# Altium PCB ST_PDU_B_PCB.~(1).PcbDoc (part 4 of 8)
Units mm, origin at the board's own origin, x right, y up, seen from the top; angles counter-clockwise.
Board outline 200 x 200 mm, 6 copper layers (Top Layer, Layer 1, Layer 2, Layer 3, Layer 4, Bottom Layer), stack 3.194 mm thick; 894 components, 723 nets, 3233 pads, 4067 vias.
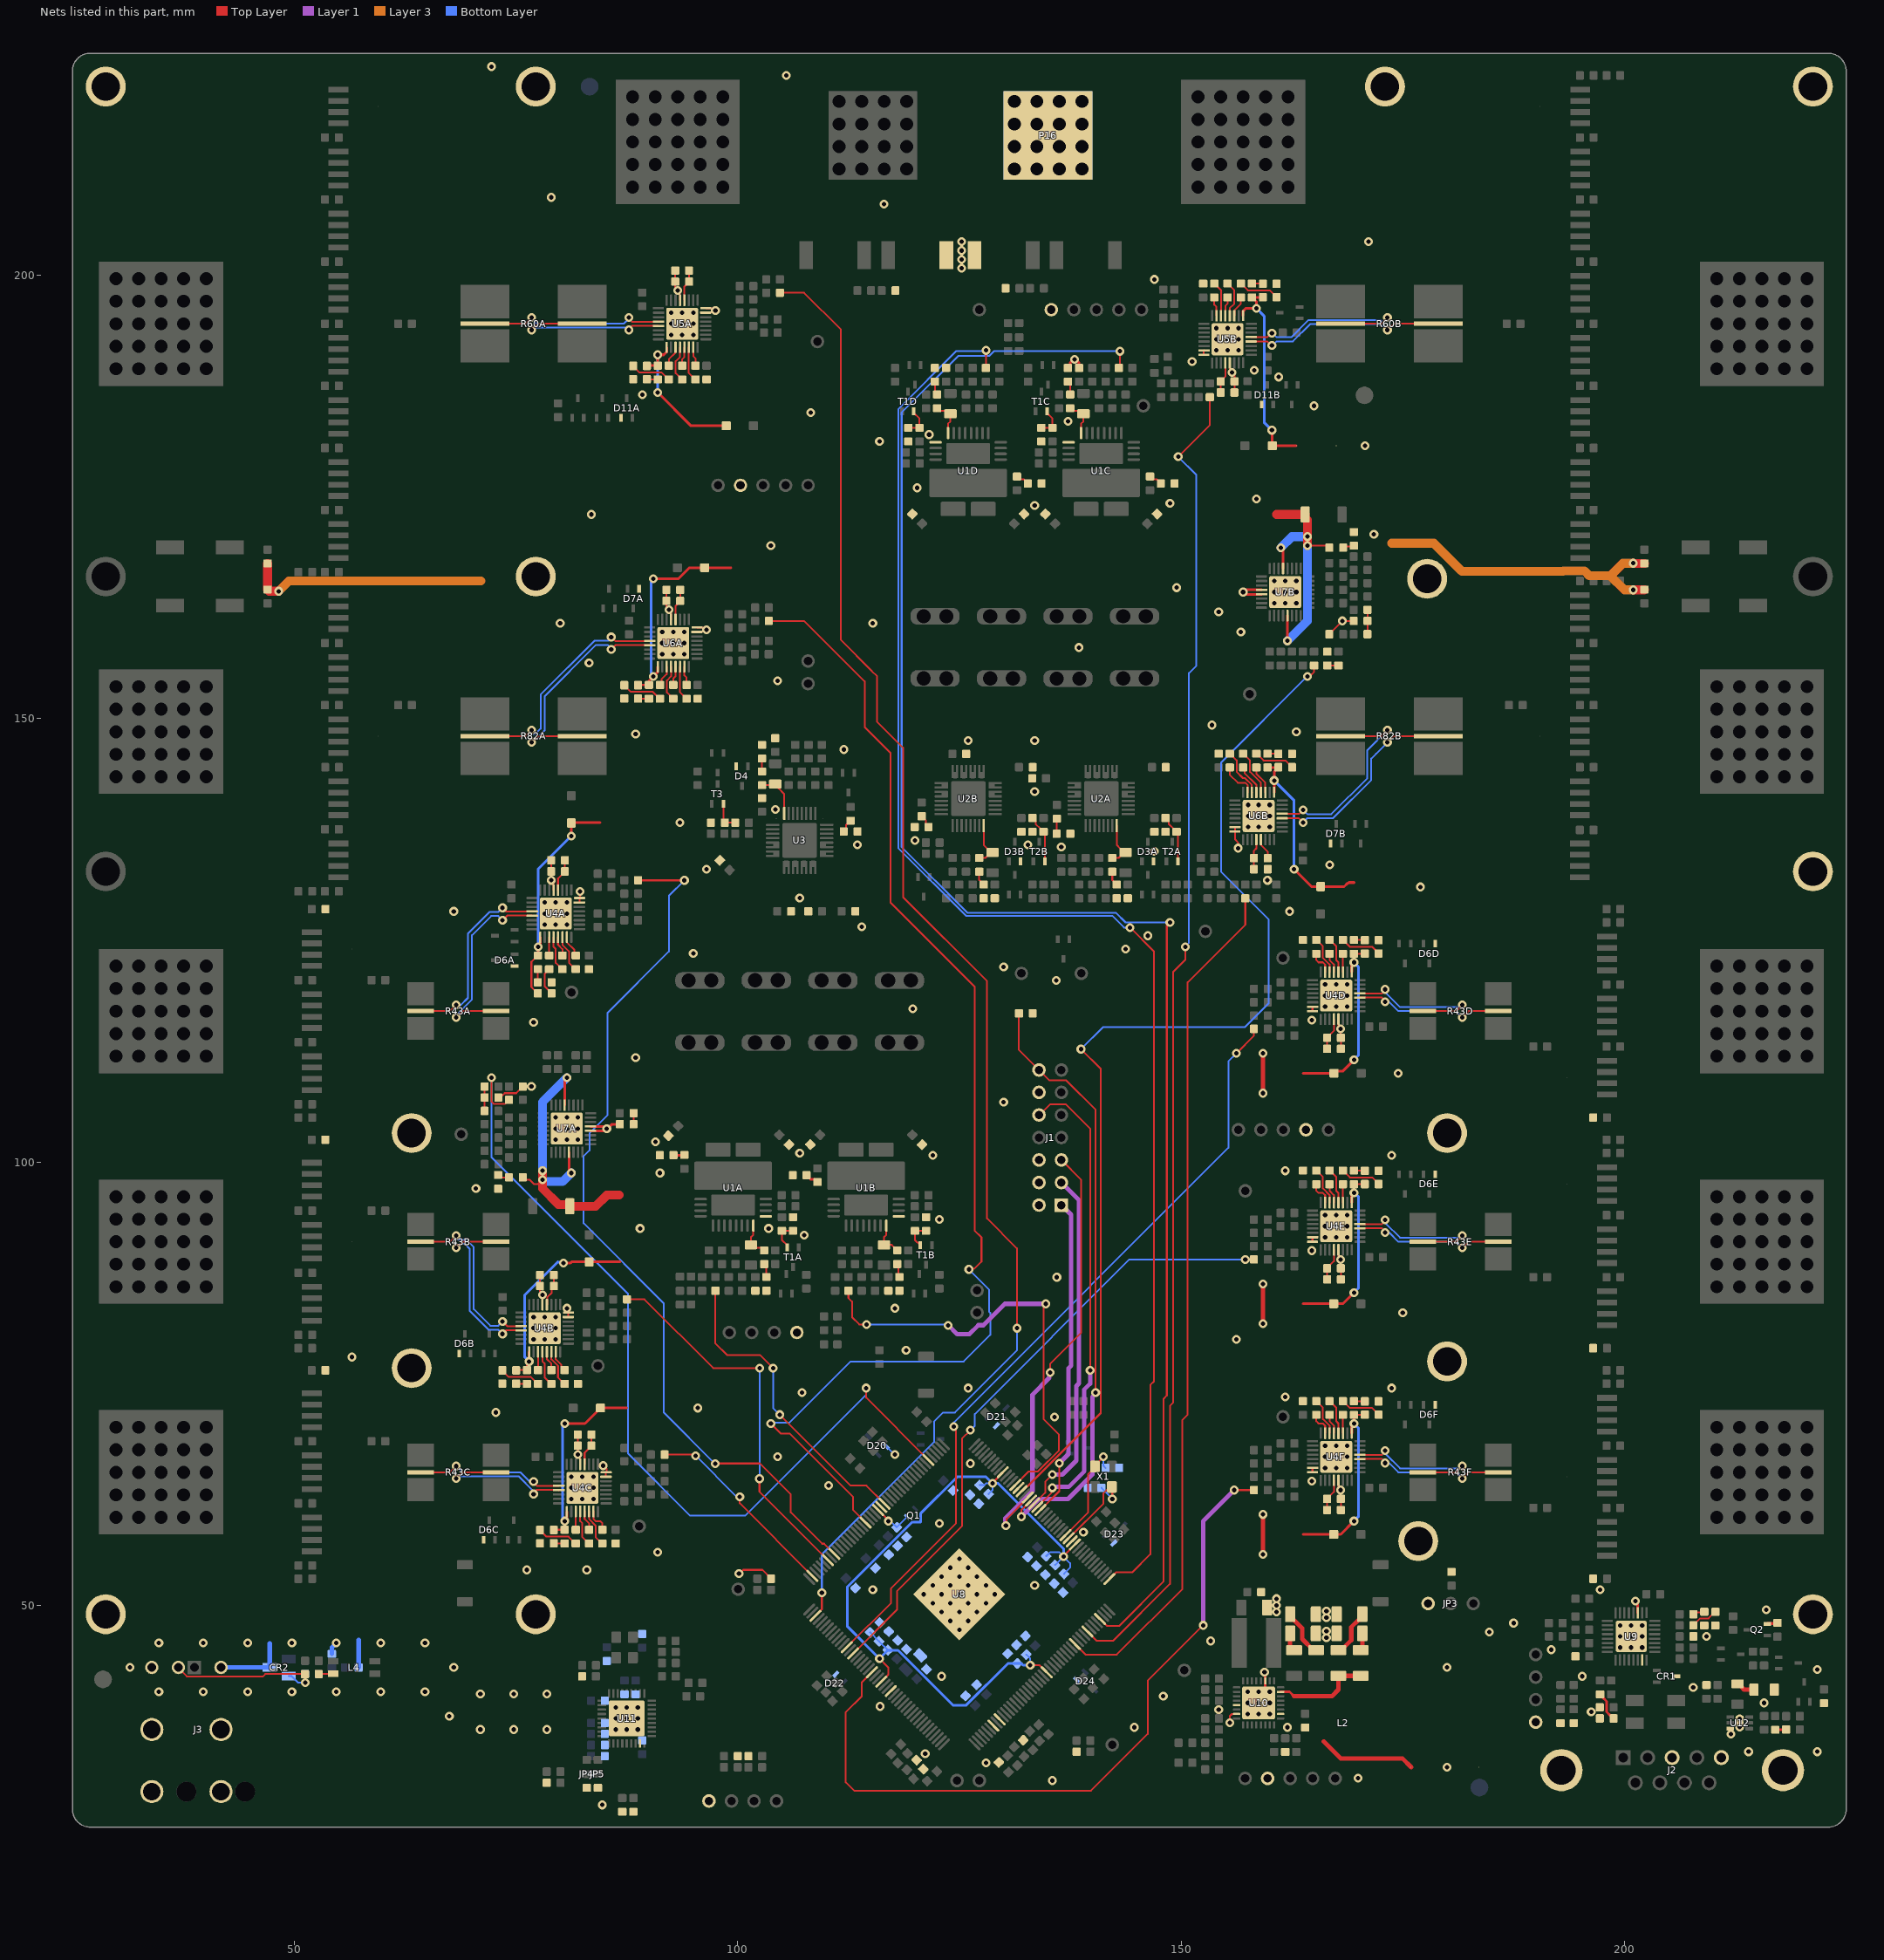
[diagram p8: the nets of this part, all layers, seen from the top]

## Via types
v1: diameter 0.65/1/1/1/1/0.65 (per signal layer), hole 0.5, Top Layer to Bottom Layer, 3739 vias
v2: diameter 0.65/1/1/1/1/0.65 (per signal layer), hole 0.5, Top Layer to Bottom Layer, tented both sides, 296 vias
v3: diameter 0.65, hole 0.5, Top Layer to Bottom Layer, 32 vias

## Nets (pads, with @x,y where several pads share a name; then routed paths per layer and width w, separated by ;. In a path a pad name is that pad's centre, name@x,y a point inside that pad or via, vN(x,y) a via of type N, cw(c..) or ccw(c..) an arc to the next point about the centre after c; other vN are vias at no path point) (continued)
GND: C1A.1 C1B.1 C1C.1 C1D.1 C4A.1 C4B.1 C4C.1 C4D.1 C5A.1 C5B.1 C5C.1 C5D.1 C6A.1 C6B.1 C6C.1 C6D.1 C7A.1 C7B.1 C7C.1 C7D.1 C8A.1 C8B.1 C11A.1 C11B.1 C12A.1 C12B.1 C13A.1 C13B.1 C14A.1 C14B.1 C15.1 C18.1 C19.1 C20.1 C21.1 C22.1 C23.1 C25A.1 C25B.1 C25C.1 C25D.1 C25E.1 C25F.1 C30A.2 C30B.2 C30C.2 C30D.2 C30E.2 C30F.2 C31A.1 C31B.1 C31C.1 C31D.1 C31E.1 C31F.1 C32A.1 C32B.1 C32C.1 C32D.1 C32E.1 C32F.1 C33A.1 C33B.1 C33C.1 C33D.1 C33E.1 C33F.1 C35A.1 C35B.1 C40A.2 C40B.2 C41A.1 C41B.1 C42A.1 C42B.1 C43A.1 C43B.1 C45A.1 C45B.1 C50A.2 C50B.2 C51A.1 C51B.1 C52A.1 C52B.1 C53A.1 C53B.1 C55A.2 C55B.2 C56A.1 C56B.1 C57A.1 C57B.1 C58A.1 C58B.1 C59A.1 C59B.1 C60.2 C61.2 C62.1 C63.1 C64.1 C65.1 C66.1 C67.1 C68.1 C69.1 C70.1 C71.1 C72.1 C73.1 C74.1 C75.1 C76.1 C77.1 C78.1 C79.1 C80.1 C81.1 C82.1 C83.1 C84.1 C85.1 C86.1 C87.1 C90.1 C91.1 C92.1 C95.2 C98.2 C99.1 C100.1 C101.1 C102.1 C103.1 C104.1 C106.1 C107.1 C109.1 C110.1 C113.1 C114.1 C115.1 C116.1 C117.1 C118.1 C119.1 C120.1 C121.1 C123.1 C124.1 C125A.2 C125B.2 C125C.2 C125D.2 C125E.2 C125F.2 C126A.2 C126B.2 C127A.2 C127B.2 CR1.3 CR2.3 D3A.2 D3B.2 D4.2 D6A.1 D6B.1 D6C.1 D6D.1 D6E.1 D6F.1 D7A.1 D7B.1 D11A.1 D11B.1 D20.1 D21.1 D22.1 D23.1 D24.1 Designator63.1 Designator63_1.1 Designator64.1 Designator64_1.1 Designator65_1.1 Designator67.1 Designator67_1.1 Designator68.1 Designator68_1.1 Designator69.1 Designator69_1.1 Designator70.1 Designator70_1.1 Designator71.1 Designator71_1.1 J1.2 J1.4 J1.6 J1.12 J2.3 J2.5 J2.10 J2.11 J3.S1 J3.S2 J3.S3 J3.S4 J3.S5 J3.S6 JP3.2 JP4.2 JP5.3 LED1.C LED2.C LED3.C LED4.C LED5.C LED6.C LED7.C LED8.C LED9.C P16.1 Q2.2 R2A.2 R2B.2 R2C.2 R2D.2 R16A.2 R16B.2 R28A.2 R28B.2 R30.2 R42.2 R71.1 R134.2 R149.2 R150.2 R151.2 R166.2 R173.2 R174.1 R175.1 R179.2 R180.1 R183.1 R189.1 R201.1 R203.1 TP7.1 TP8.1 TP10.1 TP11.1 TP22.1 TP23.1 TP50.1 Tr_d20.C Tr_d21.C U1A.1 U1B.1 U1C.1 U1D.1 U4A.7 U4A.8 U4A.13 U4A.33 U4B.7 U4B.8 U4B.13 U4B.33 U4C.7 U4C.8 U4C.13 U4C.33 U4D.7 U4D.8 U4D.13 U4D.33 U4E.7 U4E.8 U4E.13 U4E.33 U4F.7 U4F.8 U4F.13 U4F.33 U5A.7 U5A.8 U5A.13 U5A.33 U5B.7 U5B.8 U5B.13 U5B.33 U6A.7 U6A.8 U6A.13 U6A.33 U6B.7 U6B.8 U6B.13 U6B.33 U7A.20 U7A.21 U7A.33 U7B.20 U7B.21 U7B.33 U8.0 U8.27 U8.51 U8.53 U8.101 U8.118 U8.153 U9.11 U9.31 U9.33 U10.3 U10.13 U10.15 U10.26 U10.33 U11.26 U11.37 U12.0 U12.3 | length 170
  Top Layer w0.2: C57A.1@73.025,107 73.025,107.025 73.75,107.75 75.05,107.75 75.775,108.475 C58A.1@75.775,108.5 v1(76.75,108.5) ; C33B.1@77.725,87.25 C25B.1@77.725,86 77.725,85.397 78,85.122 v1(78,85) U4B.13@78,83.902 ; C33A.1@78.975,134 C25A.1@78.975,132.75 79,132.725 v1(79,131.75) 79.25,131.5 U4A.13@79.25,130.652 ; v1(80.75,83.5) 80.75,83.027 80.777,83 U4B.8@80.927,83 80.927,82.525 U4B.7@80.902,82.5 ; C33C.1@81.975,69.25 C25C.1@81.975,68 82,67.975 v1(82,67) 82.25,66.75 U4C.13@82.25,65.902 ; U4A.7@82.152,129.25 82.177,129.275 U4A.8@82.177,129.75 82.223,129.75 82.25,129.777 v1(82.25,130.5) ; v1(84.852,65.75) 84.925,65.75 85.25,65.425 85.25,65.027 85.207,65.027 85.152,64.973 U4C.7@85.152,64.5 ; C53A.1@91.975,164.5 C45A.1@91.975,163.25 91.975,162.575 92.25,162.3 v1(92.25,162.25) 92.5,162 U6A.13@92.5,161.152 ; C35A.1@92.975,200.5 C43A.1@92.975,199.25 92.975,198.575 93.25,198.3 v1(93.25,198.25) 93.5,198 U5A.13@93.5,197.152 ; U6A.7@95.402,159.75 95.429,159.777 96.277,159.777 v1(96.5,160) 96.277,160.223 95.454,160.223 U6A.8@95.427,160.25 ; U5A.7@96.402,195.75 96.429,195.777 97.276,195.777 97.499,196 v1(97.5,196) 97.277,196.223 96.454,196.223 U5A.8@96.427,196.25 ; v1(100.157,53.593) 100.227,53.593 100.634,54 102.8,54 103.775,53.025 LED2.C@103.775,53 ; U5B.8@152.573,191 152.573,191.475 U5B.7@152.598,191.5 ; v1(155.5,36.75) 155.5,37.5 155.75,37.75 U10.15@156.273,37.75 ; U5B.13@155.5,190.098 155.5,189.25 v1(155.75,189) 155.75,188.95 156.025,188.675 C43B.1@156.025,188 C35B.1@156.025,186.75 ; U6B.7@156.098,137.75 156.073,137.725 U6B.8@156.073,137.25 156.1,137.223 156.1,136.346 156.425,136.022 v1(156.425,135.377) ; U6B.13@159,136.348 159.027,136.321 159.027,135.723 159.775,134.975 C45B.1@159.775,134.25 ; U4F.8@164.823,65 164.823,65.475 U4F.7@164.848,65.5 ; U4E.8@164.823,91 164.823,91.475 U4E.7@164.848,91.5 ; U4D.8@164.823,117 164.823,117.475 U4D.7@164.848,117.5 ; C58B.1@166.725,159.5 166.725,159.525 v1(168.2,161) C57B.1@169.475,161 ; U4F.13@167.75,64.098 167.75,63.25 v1(168,63) 168,62.025 C25F.1@168.025,62 C33F.1@168.025,60.75 ; U4E.13@167.75,90.098 167.75,89.25 v1(168,89) 168,88.025 C25E.1@168.025,88 C33E.1@168.025,86.75 ; U4D.13@167.75,116.098 167.75,115.25 v1(168,115) 168,114.025 C25D.1@168.025,114 C33D.1@168.025,112.75
  Top Layer w0.3: U7A.20@83.402,103.5 84.905,103.5 v1@85.155,103.75 ; U7A.21@83.402,104 84.905,104 v1@85.155,103.75 ; C59A.1@86.725,104.25 85.845,104.25 85.345,103.75 v1(85.25,103.75) v1@85.155,103.75 ; R2C.2@137.25,189.525 137.521,189.796 137.521,190.149 137.805,190.433 137.933,190.433 v1(138,190.5) 138.074,190.5 138.5,190.074 C1C.1@138.5,189.525 ; v1(157.008,164.251) 157.093,164.251 v1@157.095,164.25 ; U7B.21@159.098,164 157.345,164 v1@157.095,164.25 ; U7B.20@159.098,164.5 157.345,164.5 v1@157.095,164.25 ; v1(159.417,42.475) 159.417,42.38 159.5,42.297 159.5,40.697 159.947,40.25 v1(160,40.25) ; v1(201.25,50.5) 201.25,50.413 201.5,50.163 U9.11@201.5,49.152 ; Q2.2@216.108,47.9 216.162,47.953 217.178,47.953 R173.2@217.25,48.025 ; C106.1@217,35.975 217.012,35.987 218.212,35.987 R201.1@218.225,36
  Top Layer w0.5: v1(159.25,55.75) C125F.2@159.25,58 v1(159.25,60.25) ; v1(159.25,81.75) C125E.2@159.25,84 v1(159.25,86.25) ; v1(159.25,107.75) C125D.2@159.25,110 v1(159.25,112.25)
  Top Layer w1: C42A.1@47,167.475 C52A.1@47,164.525 47.182,164.343 v1(48.25,164.343) ; v1(201,164.5) 202.225,164.5 C52B.1@202.25,164.525 ; v1(201,167.5) 201.025,167.475 C42B.1@202.25,167.475
  Layer 3 w1: v1(48.25,164.343) 49.407,165.5 71.061,165.5 ; 173.75,169.75 178.5,169.75 181.65,166.6 193.08,166.6 193.13,166.65 195.49,166.65 196.054,166.086 198.414,166.086 ; v1(201,164.5) 200,164.5 198.414,166.086 ; v1(201,167.5) 199.828,167.5 198.414,166.086
  Bottom Layer w0.2: D20.1@116.743,67.926 116.784,67.926 117.71,67 v1(117.75,67)
  Bottom Layer w0.5: J3.S2@41.75,43 CR2.3@47.25,43 47.25,45.714 47.244,45.72 ; C117.1@54.25,44.525 54.25,45.25 v1(54.75,45.75) ; R183.1@57.275,43 57.275,46.103
  other v1: 84.75,27.5 135.5,30.25 169.959,30.527 180,31.75 128,32.25 121.158,33.274 214,33.5 221.75,33.5 212,35.5 71,36 74.75,36 78.5,36 86.25,36 87.5,36 88.75,36 144.75,36.25 162,36.25 213,36.3 213,37.2 86.25,37.25 87.5,37.25 88.75,37.25 67.5,37.5 157.5,37.75 158.75,37.75 160,37.75 196.25,38 154.25,38.25 86.25,38.5 87.5,38.5 88.75,38.5 116.078,38.608 157.5,39 158.75,39 160,39 215.75,39 148,39.75 71,40 74.75,40 78.5,40 34.75,40.25 39.75,40.25 44.75,40.25 49.75,40.25 54.75,40.25 59.75,40.25 64.75,40.25 157.5,40.25 158.75,40.25 207.75,40.75 123,42 195.25,42 221.75,42.75 31.5,43 68,43 180,43 191.75,45 199.5,45.25 200.75,45.25 202,45.25 34.75,45.75 39.75,45.75 44.75,45.75 49.75,45.75 59.75,45.75 64.75,45.75 153.333,45.986 166.4,46.35 199.5,46.5 200.75,46.5 202,46.5 209.25,46.5 184.75,47 166.4,47.1 125,47.25 199.5,47.75 200.75,47.75 202,47.75 187.5,48 124,48.25 126,48.25 166.4,48.6 123,49.25 125,49.25 127,49.25 160.75,49.25 166.4,49.35 216,49.5 160.75,50 122,50.25 124,50.25 126,50.25 128,50.25 160.75,50.75 121,51.25 123,51.25 125,51.25 127,51.25 129,51.25 115.25,51.75 197.25,51.75 122,52.25 124,52.25 126,52.25 128,52.25 133.5,52.25 123,53.25 125,53.25 127,53.25 76.25,54 83,54 124,54.25 126,54.25 125,55.25 91,56 139,58.25 122.75,59.25 81.25,62 82.5,62 83.75,62 81.25,63.25 82.5,63.25 83.75,63.25 110.25,63.5 164.75,64 81.25,64.5 82.5,64.5 83.75,64.5 166.25,65.5 167.5,65.5 168.75,65.5 126.25,66 104.5,66.75 166.25,66.75 167.5,66.75 168.75,66.75 166.25,68 167.5,68 168.75,68 135.75,71.25 72.75,71.75 95.5,72.25 161.75,73.5 107.25,74 126,74.5 173.75,74.5 56.5,78 119,78.75 77,80 78.25,80 79.5,80 156.25,80 77,81.25 78.25,81.25 79.5,81.25 77,82.5 78.25,82.5 79.5,82.5 175,83 117.75,83.5 136,87 164.75,90 166.25,91.5 167.5,91.5 168.75,91.5 107.5,91.75 89,92.5 103.5,92.5 166.25,92.75 167.5,92.75 168.75,92.75 122.75,93.5 166.25,94 167.5,94 168.75,94 70.5,97 91.25,98.75 161.75,99 122,100.75 173.75,100.75 107,101 90.75,102.25 79.5,102.5 80.75,102.5 82,102.5 79.5,103.75 80.75,103.75 82,103.75 79.5,105 80.75,105 82,105 130,106.75 174.5,110 88.5,111.75 77,115.75 164.75,116 119.75,117.25 166.25,117.5 167.5,117.5 168.75,117.5 166.25,118.75 167.5,118.75 168.75,118.75 166.25,120 167.5,120 168.75,120 135.946,120.45 130,122 95,123.5 143.75,124 146.25,125.5 114,126.5 78.25,126.75 79.5,126.75 80.75,126.75 78.25,128 79.5,128 80.75,128 68,128.25 162.25,128.25 78.25,129.25 79.5,129.25 80.75,129.25 107,129.75 177,131 159.75,131.75 96.5,133 166.75,133.5 147,135 136.5,135.5 113.5,135.75 132.75,135.75 120,136.25 157.575,137.75 158.75,137.75 160,137.75 93.5,138.25 157.575,139 158.75,139 160,139 104.25,139.75 157.575,140.25 158.75,140.25 160,140.25 133.5,141.75 112,146.5 126,147.5 133.5,147.5 88.5,148.25 163,148.5 153.5,149.25 104.5,154.25 83.25,156.25 91.5,157.25 92.75,157.25 94,157.25 138.5,158 91.5,158.5 92.75,158.5 94,158.5 91.5,159.75 92.75,159.75 94,159.75 156.75,159.75 80,160.75 115.25,160.75 154.25,162 160.5,163 161.75,163 163,163 160.5,164.25 161.75,164.25 163,164.25 149.5,164.75 160.5,165.5 161.75,165.5 163,165.5 103.75,169.5 171.75,170.75 83.5,173 133.5,174 148.75,174.25 158.5,174.75 120.25,176 170.75,180.75 116,181.25 121.6,182 137.25,183.5 108.25,184.5 165,185.25 89.25,186.5 161,188.5 158.25,189.25 151.25,190.25 154,191.5 155.25,191.5 156.5,191.5 154,192.75 155.25,192.75 156.5,192.75 92.5,193.25 93.75,193.25 95,193.25 154,194 155.25,194 156.5,194 92.5,194.5 93.75,194.5 95,194.5 92.5,195.75 93.75,195.75 95,195.75 147,199.5 125.25,200.75 125.25,201.75 125.25,202.75 125.25,203.75 171.133,203.746 116.5,208 79,208.75 105.5,222.5 72.25,223.5
HWLO_A1: R78A.2 U8.3 | length 172
  Top Layer w0.2: R78A.2@104.775,198 107.5,198 111.65,193.85 111.65,159 111.65,158.855 115.128,155.378 115.128,155.367 115.733,154.762 115.733,149.612 118.65,146.695 118.65,129.85 128.13,120.37 128.13,93.62 131.5,90.25 v1(131.5,81.25) ; U8.3@108.783,48.821 108.783,48.848 109.5,49.566 v1(109.5,51.425)
  Bottom Layer w0.2: v1(109.5,51.425) 109.5,55.75 122.155,68.405 122.155,70.719 123.187,71.75 124.5,71.75 131.5,78.75 v1(131.5,81.25)
HWLO_A2: R98A.2 U8.158 | length 139.7
  Top Layer w0.2: R98A.2@103.525,161 107.505,161 114.333,154.172 114.333,149.032 117.25,146.115 117.25,129.25 126.73,119.77 126.73,92.27 127.5,91.5 127.5,88.762 126.704,87.966 126.16,87.966 v1(126.079,87.885) ; v1(103.75,70.5) 104.9,69.35 105.9,69.35 106,69.25 113,62.25 113,60.775 U8.158@114.439,59.336
  Bottom Layer w0.2: v1(103.75,70.5) 103.825,70.575 105.825,70.575 112.75,77.5 125.5,77.5 128.5,80.5 128.5,82.966 128.35,83.116 128.35,85.614 v1(126.079,87.885)
HWLO_A3: R58A.2 U8.168 | length 100.7
  Top Layer w0.2: R58A.2@88.775,131.75 88.778,131.747 v1(94.005,131.747) ; v1(97.468,65.968) 97.5,66 102.5,66 106,62.5 106,60.492 109.542,56.95 109.754,56.95 U8.168@110.904,55.8
  Bottom Layer w0.2: v1(94.005,131.747) 93.997,131.747 92.25,130 92.25,123.717 85.35,116.817 85.35,105.292 83.302,103.243 83.302,101.307 82.645,100.65 82.645,93.095 91.675,84.065 91.675,71.762 v1(97.468,65.968)
HWLO_A4: R58B.2 U8.170 | length 43.1
  Top Layer w0.2: R58B.2@87.525,84.5 89.5,84.5 97.25,76.75 v1(102.5,76.75) ; v1(102.468,64.282) 102.468,62.821 U8.170@110.197,55.093
  Bottom Layer w0.2: v1(102.468,64.282) 102.484,64.297 102.484,76.734 v1(102.5,76.75)
HWLO_A5: R58C.2 U8.175 | length 22.8
  Top Layer w0.2: R58C.2@91.775,67 95,67 95.041,66.959 95.188,66.959 v1(95.275,66.873) ; v1(100.25,62.25) 100.25,61.504 U8.175@108.429,53.325
  Bottom Layer w0.2: v1(95.275,66.873) 99.832,62.316 100.184,62.316 v1(100.25,62.25)
HWLO_B1: R78B.2 U8.81 | length 149.8
  Top Layer w0.2: U8.81@139.45,47.053 140.503,46 142.325,46 148.75,52.425 148.75,72.5 149.128,72.878 149.128,121.447 150.5,122.82 v1(150.5,124.25) ; v1(149.684,179.503) 153.25,183.069 R78B.2@153.25,186.225
  Bottom Layer w0.2: v1(149.684,179.503) 151.731,177.456 151.731,155.938 150.903,155.11 150.903,124.73 150.5,124.327 v1(150.5,124.25)
HWLO_B2: R98B.2 U8.77 | length 96.5
  Top Layer w0.2: U8.77@138.036,45.639 139.225,44.45 142.755,44.45 150.15,51.845 150.15,70.9 150.75,71.5 150.75,120.25 157.25,126.75 R98B.2@157.25,129.725
HWLO_B3: R58D.2 U8.13 | length 88.9
  Top Layer w0.2: U8.13@112.318,45.286 117.3,50.268 117.3,51.919 124.6,59.219 124.6,69.818 124.37,70.048 v1(124.37,70.16) ; v1(156.25,112.25) 158.225,114.225 R58D.2@158.225,115
  Bottom Layer w0.2: v1(124.37,70.16) 124.382,70.172 124.382,70.632 155.348,101.598 155.348,111.348 v1(156.25,112.25)
HWLO_B4: R58E.2 U8.15 | length 71.4
  Top Layer w0.2: U8.15@113.025,44.578 118,49.553 118,51.629 125.3,58.929 125.3,68.8 v1(126.25,69.75) ; v1(157.25,89) R58E.2@158.225,89
  Bottom Layer w0.2: v1(126.25,69.75) 126.75,70.25 126.75,71.575 144.175,89 v1(157.25,89)
HWLO_B5: R58F.2 U8.21 | length 84.5
  Top Layer w0.2: U8.21@115.146,42.457 114,41.311 114,39.75 112.2,37.95 112.2,30.05 113.15,29.1 139.85,29.1 146.25,35.5 146.25,41.5 v1(152.5,47.75) ; v1(156,63) R58F.2@158.225,63
  Layer 1 w0.5: v1(152.5,47.75) 152.5,59.5 v1(156,63)
ISNS3A_N: R43A.3 U4A.20 | length 21.9
  Top Layer w0.2: R43A.3@64.25,117 67.573,117 v1(68.273,117.7) ; v1(73.5,128.65) 73.923,128.227 76.825,128.227 U4A.20@76.848,128.25
  Bottom Layer w0.2: v1(68.273,117.7) 68.296,117.677 68.78,117.677 69.6,118.497 69.6,125.742 72.035,128.177 73.027,128.177 v1(73.5,128.65)
ISNS3A_P: R43A.4 U4A.21 | length 22.9
  Top Layer w0.2: v1(68.273,116.3) 68.973,117 R43A.4@72.75,117 ; v1(73.5,127.25) 74.023,127.773 76.825,127.773 U4A.21@76.848,127.75
  Bottom Layer w0.2: v1(68.273,116.3) 68.359,116.386 68.359,116.614 70.054,118.309 70.054,125.554 72.223,127.723 73.027,127.723 v1(73.5,127.25)
ISNS3B_N: R43B.3 U4B.20 | length 20.5
  Top Layer w0.2: R43B.3@64.25,91 67.573,91 v1(68.273,91.7) ; v1(73.5,82) 74.023,81.477 75.575,81.477 U4B.20@75.598,81.5
  Bottom Layer w0.2: v1(68.273,91.7) 68.359,91.614 68.359,91.386 68.518,91.227 69.415,91.227 70.25,90.392 70.25,83.392 72.115,81.527 73.027,81.527 v1(73.5,82)
ISNS3B_P: R43B.4 U4B.21 | length 20.8
  Top Layer w0.2: v1(68.273,90.3) 68.973,91 R43B.4@72.75,91 ; v1(73.5,80.6) 73.923,81.023 75.575,81.023 U4B.21@75.598,81
  Bottom Layer w0.2: v1(68.273,90.3) 68.273,90.362 68.684,90.773 69.227,90.773 69.796,90.204 69.796,83.204 71.927,81.073 73.027,81.073 v1(73.5,80.6)
ISNS3C_N: R43C.3 U4C.20 | length 16.9
  Top Layer w0.2: R43C.3@64.25,65 67.573,65 v1(68.273,65.7) ; v1(77,63.95) 77,63.828 77.351,63.477 79.825,63.477 U4C.20@79.848,63.5
  Bottom Layer w0.2: v1(68.273,65.7) 68.973,65 75.5,65 76.533,63.967 76.983,63.967 v1(77,63.95)
ISNS3C_P: R43C.4 U4C.21 | length 17.7
  Top Layer w0.2: v1(68.273,64.3) 68.973,65 R43C.4@72.75,65 ; v1(77,62.55) 77,62.672 77.351,63.023 79.825,63.023 U4C.21@79.848,63
  Bottom Layer w0.2: v1(68.273,64.3) 68.369,64.3 68.615,64.546 75.312,64.546 76.914,62.944 76.914,62.636 v1(77,62.55)
ISNS3D_N: R43D.3 U4D.20 | length 16.9
  Top Layer w0.2: U4D.20@170.152,118.5 170.175,118.523 172.649,118.523 173,118.172 v1(173,118.05) ; v1(181.727,116.3) 182.427,117 R43D.3@185.75,117
  Bottom Layer w0.2: v1(173,118.05) 173.017,118.033 173.467,118.033 174.5,117 181.027,117 v1(181.727,116.3)
ISNS3D_P: R43D.4 U4D.21 | length 17.7
  Top Layer w0.2: U4D.21@170.152,119 170.175,118.977 172.649,118.977 173,119.328 v1(173,119.45) ; R43D.4@177.25,117 181.027,117 v1(181.727,117.7)
  Bottom Layer w0.2: v1(173,119.45) 173.086,119.364 173.086,119.056 174.688,117.454 181.385,117.454 181.631,117.7 v1(181.727,117.7)
ISNS3E_N: R43E.3 U4E.20 | length 16.9
  Top Layer w0.2: U4E.20@170.152,92.5 170.175,92.523 172.649,92.523 173,92.172 v1(173,92.05) ; v1(181.727,90.3) 182.427,91 R43E.3@185.75,91
  Bottom Layer w0.2: v1(173,92.05) 173.017,92.033 173.467,92.033 174.5,91 181.027,91 v1(181.727,90.3)
ISNS3E_P: R43E.4 U4E.21 | length 17.7
  Top Layer w0.2: U4E.21@170.152,93 170.175,92.977 172.649,92.977 173,93.328 v1(173,93.45) ; R43E.4@177.25,91 181.027,91 v1(181.727,91.7)
  Bottom Layer w0.2: v1(173,93.45) 173.086,93.364 173.086,93.056 174.688,91.454 181.385,91.454 181.631,91.7 v1(181.727,91.7)
ISNS3F_N: R43F.3 U4F.20 | length 16.9
  Top Layer w0.2: U4F.20@170.152,66.5 170.175,66.523 172.649,66.523 173,66.172 v1(173,66.05) ; v1(181.727,64.3) 182.427,65 R43F.3@185.75,65
  Bottom Layer w0.2: v1(173,66.05) 173.017,66.033 173.467,66.033 174.5,65 181.027,65 v1(181.727,64.3)
ISNS3F_P: R43F.4 U4F.21 | length 17.7
  Top Layer w0.2: U4F.21@170.152,67 170.175,66.977 172.649,66.977 173,67.328 v1(173,67.45) ; R43F.4@177.25,65 181.027,65 v1(181.727,65.7)
  Bottom Layer w0.2: v1(173,67.45) 173.086,67.364 173.086,67.056 174.688,65.454 181.385,65.454 181.631,65.7 v1(181.727,65.7)
ISNS5A_N: R82A.3 U6A.20 | length 26.3
  Top Layer w0.2: R82A.3@71.5,148 76.073,148 v1(76.773,148.7) ; v1(85.75,159.177) 86.2,158.727 90.075,158.727 U6A.20@90.098,158.75
  Bottom Layer w0.2: v1(76.773,148.7) 76.859,148.614 76.859,148.386 77.018,148.227 77.184,148.227 77.796,148.839 77.796,152.688 83.858,158.75 85.445,158.75 85.75,159.055 v1(85.75,159.177)
ISNS5A_P: R82A.4 U6A.21 | length 26.8
  Top Layer w0.2: v1(76.773,147.3) 77.473,148 R82A.4@82.5,148 ; v1(85.75,157.777) 86.246,158.273 90.075,158.273 U6A.21@90.098,158.25
  Bottom Layer w0.2: v1(76.773,147.3) 76.859,147.386 76.859,147.614 77.018,147.773 77.372,147.773 78.25,148.651 78.25,152.5 84.046,158.296 85.353,158.296 85.75,157.899 v1(85.75,157.777)
ISNS5B_N: R82B.3 U6B.20 | length 23.3
  Top Layer w0.2: U6B.20@161.402,138.75 161.425,138.773 163.254,138.773 v1(163.75,138.277) ; v1(173.273,147.3) 173.973,148 R82B.3@179,148
  Bottom Layer w0.2: v1(163.75,138.277) 163.777,138.277 164.25,138.75 167.142,138.75 171.454,143.062 171.454,145.481 171.99,146.017 v1(173.273,147.3)
ISNS5B_P: R82B.4 U6B.21 | length 23.6
  Top Layer w0.2: U6B.21@161.402,139.25 161.425,139.227 163.3,139.227 v1(163.75,139.677) ; R82B.4@168,148 172.573,148 v1(173.273,148.7)
  Bottom Layer w0.2: v1(163.75,139.677) 163.777,139.677 164.25,139.204 166.954,139.204 171,143.25 171,146.427 v1(173.273,148.7)
ISNS8A_N: R60A.3 U5A.20 | length 20.9
  Top Layer w0.2: R60A.3@71.5,194.5 76.073,194.5 v1(76.773,195.2) ; v1(87.75,195.2) 87.75,195.078 88.101,194.727 91.075,194.727 U5A.20@91.098,194.75
  Bottom Layer w0.2: v1(76.773,195.2) 76.773,195.078 77.322,194.529 87.201,194.529 87.75,195.078 v1(87.75,195.2)
ISNS8A_P: R60A.4 U5A.21 | length 20.8
  Top Layer w0.2: v1(76.773,193.8) 77.473,194.5 R60A.4@82.5,194.5 ; v1(87.75,193.8) 87.75,193.922 88.101,194.273 91.075,194.273 U5A.21@91.098,194.25
  Bottom Layer w0.2: v1(76.773,193.8) 76.84,193.8 77.115,194.075 87.408,194.075 87.683,193.8 v1(87.75,193.8)
ISNS8B_N: R60B.3 U5B.20 | length 23.1
  Top Layer w0.2: U5B.20@157.902,192.5 157.925,192.523 159.727,192.523 v1@160.312,191.938 ; v1(173.273,193.8) 173.973,194.5 R60B.3@179,194.5
  Bottom Layer w0.2: v1@160.252,192.002 160.773,192.523 162.628,192.523 164.576,194.471 172.284,194.471 172.482,194.273 172.922,194.273 173.273,193.922 v1(173.273,193.8)
  other v1: 160.25,192.05
ISNS8B_P: R60B.4 U5B.21 | length 22.3
  Top Layer w0.2: U5B.21@157.902,193 157.925,192.977 159.727,192.977 v1@160.332,193.582 ; R60B.4@168,194.5 172.573,194.5 v1(173.273,195.2)
  Bottom Layer w0.2: v1@160.436,193.314 160.773,192.977 162.44,192.977 164.388,194.925 172.472,194.925 172.652,194.745 172.818,194.745 v1(173.273,195.2)
  other v1: 160.25,193.45
JTAG_JCOMP: J1.14 R134.1 U8.114 | length 69.1
  Top Layer w0.2: R134.1@131.725,116.75 131.725,112.625 J1.14@133.98,110.37 135.167,109.183 137.067,109.183 140.375,105.875 v1(140.375,74) ; v1(132,60) 132,60.725 U8.114@133.086,61.811
  Layer 1 w0.5: v1(132,60) 134,62 137.25,62 140,64.75 140,73.49 140.375,73.865 v1(140.375,74)
JTAG_TCK: J1.5 U8.115 | length 49.9
  Top Layer w0.2: v1(130.25,59) 130.336,59.086 130.336,59.768 U8.115@132.732,62.164 ; v1(135.25,76.25) 135.25,77.25 138.75,80.75 138.75,97.98 J1.5@136.52,100.21
  Layer 1 w0.5: v1(130.25,59) 130.196,59.054 130.196,59.822 133.25,62.876 133.25,73.75 135.154,75.654 135.154,76.154 v1(135.25,76.25)
JTAG_TDI: J1.1 U8.111 | length 36.3
  Top Layer w0.2: U8.111@134.146,60.75 136.277,62.88 v1(136.277,66.024)
  Layer 1 w0.5: v1(136.277,66.024) 137.3,67.047 137.3,76.725 137.594,77.019 137.594,94.056 J1.1@136.52,95.13
JTAG_TDO: J1.3 U8.113 | length 39.8
  Top Layer w0.2: U8.113@133.439,61.457 134.683,62.701 134.683,63.933 v1(135.5,64.75)
  Layer 1 w0.5: v1(135.5,64.75) 136.629,64.75 138.2,66.321 138.2,74.724 138.494,75.018 138.494,95.696 J1.3@136.52,97.67
JTAG_TMS: J1.10 U8.112 | length 53.5
  Top Layer w0.2: U8.112@133.793,61.104 135.414,62.725 135.414,63.164 v1(135.5,63.25) ; J1.10@133.98,105.29 134.04,105.29 135.25,106.5 137,106.5 139.75,103.75 v1(139.75,76.5)
  Layer 1 w0.5: v1(135.5,63.25) 135.6,63.35 137.327,63.35 139.1,65.123 139.1,74.351 139.75,75.001 v1(139.75,76.5)
LH_A6: R10A.2 U8.152 | length 35.1
  Top Layer w0.2: R10A.2@97.5,85.475 97.5,79.538 98.806,78.232 102.518,78.232 v1(104,76.75) ; v1(104.75,71.5) 112.75,63.5 114.518,63.5 U8.152@116.561,61.457
  Bottom Layer w0.2: v1(104,76.75) 104,72.25 v1(104.75,71.5)
LH_A8: R10B.2 U8.119 | length 51.1
  Top Layer w0.2: R10B.2@112.5,85.475 112.5,84.65 112.9,84.25 112.9,82.5 113.725,81.675 v1(114.548,81.675) ; U8.119@131.318,63.578 132.834,65.095 133.87,65.095 136.25,67.475 136.25,69.25 134.5,71 134.5,83.658 134.75,83.908 v1(134.75,84)
  Layer 1 w0.5: v1(123.75,81.575) 124.757,80.568 126.129,80.568 127.148,81.588 127.712,81.588 130.124,84 v1(134.75,84)
  Bottom Layer w0.2: v1(114.548,81.675) 123.528,81.675 123.628,81.575 v1(123.75,81.575)
LH_A14: R102A.2 U8.138 | length 100.9
  Top Layer w0.2: v1(72.25,109.5) 72.25,106.812 72.537,106.525 73.75,106.525 73.858,106.633 73.876,106.633 74.225,106.982 R102A.2@74.225,107 ; v1(114.5,74.5) 114.5,73.417 U8.138@121.51,66.407
  Bottom Layer w0.2: v1(72.25,109.5) 72.25,100.505 87.65,85.105 87.65,67.105 94.655,60.1 100.828,60.1 114.5,73.772 v1(114.5,74.5)
LH_B6: R10C.2 U8.85 | length 196.4
  Top Layer w0.2: U8.85@140.864,48.468 140.891,48.468 141.684,47.675 143.01,47.675 148.05,52.715 148.05,73.3 148.4,73.65 148.4,126.658 148.742,127 v1(148.75,127) ; R10C.2@143,189.525 143.12,189.645 v1(143.12,191.401)
  Bottom Layer w0.2: v1(143.12,191.401) 128.901,191.401 128.379,190.879 124.879,190.879 118.5,184.5 118.5,135.5 125.9,128.1 142.65,128.1 143.75,127 v1(148.75,127)
LH_B8: R10D.2 U8.89 | length 171.6
  Top Layer w0.2: R10D.2@128,189.525 v1(128,191.5) ; U8.89@141.925,52.972 142.685,53.733 144.518,53.733 146.55,55.765 146.55,74.85 146.95,75.25 146.95,123.725 v1(144.25,126.425)
  Bottom Layer w0.2: v1(128,191.5) 127.925,191.425 124.675,191.425 118.15,184.9 118.15,135.35 125.75,127.75 142.25,127.75 143.575,126.425 v1(144.25,126.425)
LH_B14: R102B.2 U8.117 | length 122.7
  Top Layer w0.2: U8.117@132.025,62.871 132.575,63.421 132.691,63.421 140.95,71.68 140.95,110.487 v1(138.718,112.718) ; v1(164.25,154.75) 164.336,154.836 164.586,154.836 165,155.25 R102B.2@165,155.975
  Bottom Layer w0.2: v1(138.718,112.718) 141.2,115.2 157.18,115.2 157.23,115.25 157.25,115.25 159.9,117.9 159.9,127.33 154.5,132.73 154.5,145 v1(164.25,154.75)
NetC2A_1: C2A.1 R2A.1 | length 1.6
  Top Layer w0.2: C2A.1@103,88.475 103.25,88.225 R2A.1@103.25,87.025
NetC2A_2: C2A.2 R1A.1 U1A.18 | length 4
  Top Layer w0.2: U1A.18@101.775,92.82 101.775,91.775 101.5,91.5 R1A.1@101.5,90.643 101.832,90.311 102.714,90.311 C2A.2@103,90.025
NetC2B_1: C2B.1 R2B.1 | length 1.6
  Top Layer w0.2: C2B.1@118,88.475 118.125,88.35 118.125,87.15 R2B.1@118.25,87.025
NetC2B_2: C2B.2 R1B.1 U1B.18 | length 4.1
  Top Layer w0.2: R1B.1@116.5,90.643 116.5,91.5 116.775,91.775 U1B.18@116.775,92.82 ; R1B.1@116.5,90.643 117.383,90.642 117.633,90.392 117.633,90.374 117.982,90.025 C2B.2@118,90.025
NetC2C_1: C2C.1 R2C.1 | length 1.6
  Top Layer w0.2: R2C.1@137.25,187.975 137.5,187.725 C2C.1@137.5,186.525
NetC2C_2: C2C.2 R1C.1 U1C.18 | length 4
  Top Layer w0.2: C2C.2@137.5,184.975 137.786,184.689 138.668,184.689 R1C.1@139,184.357 139,183.489 138.725,183.215 U1C.18@138.725,182.18
NetC2D_1: C2D.1 R2D.1 | length 1.6
  Top Layer w0.2: R2D.1@122.25,187.975 122.25,186.775 C2D.1@122.5,186.525
NetC2D_2: C2D.2 R1D.1 U1D.18 | length 4
  Top Layer w0.2: C2D.2@122.5,184.975 122.786,184.689 123.668,184.689 R1D.1@124,184.357 124,183.489 123.725,183.215 U1D.18@123.725,182.18
NetC3A_1: C3A.1 C4A.2 | length 1.2
  Top Layer w0.3: C4A.2@92.775,100.75 92.788,100.763 93.988,100.763 C3A.1@94,100.775
NetC3B_1: C3B.1 C4B.2 | length 1.6
  Top Layer w0.3: C4B.2@107.775,98.5 107.775,98.475 108.075,98.175 108.1,98.175 108.25,98.025 108.7,98.025 C3B.1@109,97.725
NetC3C_1: C3C.1 C4C.2 | length 1.6
  Top Layer w0.2: C3C.1@146.5,177.275 146.825,176.95 147.275,176.95 147.358,176.867 147.376,176.867 147.725,176.518 C4C.2@147.725,176.5
NetC3D_1: C3D.1 C4D.2 | length 1.6
  Top Layer w0.2: C3D.1@131.5,177.275 131.825,176.95 132.275,176.95 132.358,176.867 132.376,176.867 132.725,176.518 C4D.2@132.725,176.5
NetC5A_2: C5A.2 R4A.1 T1A.2 | length 3.4
  Top Layer w0.2: T1A.2@105.6,90.358 105.6,90.591 105,91.191 R4A.1@105,92.225 C5A.2@106.25,92.225
NetC5B_2: C5B.2 R4B.1 T1B.2 | length 3.4
  Top Layer w0.2: T1B.2@120.6,90.358 120.6,90.591 120,91.191 R4B.1@120,92.225 C5B.2@121.25,92.225
NetC5C_2: C5C.2 R4C.1 T1C.2 | length 3.4
  Top Layer w0.2: C5C.2@134.25,182.775 R4C.1@135.5,182.775 135.5,183.809 134.9,184.409 T1C.2@134.9,184.642
NetC5D_2: C5D.2 R4D.1 T1D.2 | length 3.4
  Top Layer w0.2: C5D.2@119.25,182.775 R4D.1@120.5,182.775 120.5,183.809 119.9,184.409 T1D.2@119.9,184.642
NetC9A_1: C9A.1 R16A.1 | length 1.7
  Top Layer w0.2: C9A.1@142.25,132.725 142.25,131.775 142.383,131.642 142.383,131.624 142.732,131.275 R16A.1@142.75,131.275
NetC9A_2: C9A.2 R15A.1 U2A.16 | length 5.1
  Top Layer w0.2: C9A.2@142.25,134.275 142.252,134.277 142.965,134.277 143.167,134.48 143.167,134.483 143.577,134.892 R15A.1@143.58,134.892 ; U2A.16@142.764,137.921 142.764,135.709 143.15,135.323 143.15,135.321 143.578,134.893 R15A.1@143.75,134.893
NetC9B_1: C9B.1 R16B.1 | length 1.7
  Top Layer w0.2: C9B.1@127.25,132.725 127.25,131.775 127.383,131.642 127.383,131.624 127.732,131.275 R16B.1@127.75,131.275
NetC9B_2: C9B.2 R15B.1 U2B.16 | length 5.1
  Top Layer w0.2: C9B.2@127.25,134.275 127.96,134.275 R15B.1@128.578,134.893 ; U2B.16@127.764,137.921 127.764,135.709 128.15,135.323 128.15,135.321 R15B.1@128.578,134.893 ; R15B.1@128.75,134.893 R15B.1@128.578,134.893
NetC10A_1: C10A.1 C11A.2 | length 1.7
  Top Layer w0.2: C11A.2@135.975,137 135.975,138.675 C10A.1@136,138.7
NetC10B_1: C10B.1 C11B.2 | length 1.6
  Top Layer w0.2: C10B.1@120.75,138.975 120.768,138.975 121.218,138.525 121.218,138.057 C11B.2@121.525,137.75
NetC12A_2: C12A.2 R18A.1 T2A.2 | length 5.5
  Top Layer w0.2: C12A.2@148.25,138.775 148.268,138.775 148.617,138.426 148.617,138.108 149.133,137.592 149.133,137.574 149.482,137.225 R18A.1@149.5,137.225 149.65,137.075 T2A.2@149.65,133.892
NetC12B_2: C12B.2 R18B.1 T2B.2 | length 5.5
  Top Layer w0.2: C12B.2@133.268,138.775 133.617,138.426 133.617,138.108 134.133,137.592 134.133,137.574 134.482,137.225 R18B.1@134.5,137.225 134.65,137.075 T2B.2@134.65,133.892
NetC16_1: C16.1 R30.1 | length 1.4
  Top Layer w0.2: C16.1@102.75,144.025 R30.1@102.75,145.475
NetC16_2: C16.2 R29.1 U3.16 | length 5.1
  Top Layer w0.2: C16.2@102.75,142.475 104.25,142.475 104.268,142.475 104.617,142.126 104.617,142.108 105.25,141.475 U3.16@105.25,139.294
NetC17_1: C17.1 C18.2 | length 1.6
  Top Layer w0.2: C18.2@111.975,137.25 112.25,137.525 112.25,138.008 112.375,138.133 112.408,138.133 C17.1@112.75,138.475
NetC19_2: C19.2 R32.1 T3.2 | length 3.7
  Top Layer w0.2: T3.2@98.4,140.392 98.4,138.4 C19.2@98.55,138.25 C19.2@98.55,138.488 ; C19.2@98.537,138.488 98.775,138.25 R32.1@99.725,138.25
NetC24A_1: C24A.1 U4A.30 | length 4.3
  Top Layer w0.2: U4A.30@80.25,125.348 80.25,124.488 81,123.738 81,122.45 81.725,121.725 C24A.1@81.75,121.725
NetC24A_2: C24A.2 U4A.31 | length 2.5
  Top Layer w0.2: U4A.31@80.75,125.348 80.777,125.321 80.777,124.723 81.592,123.908 81.592,123.433 C24A.2@81.75,123.275
NetC24B_1: C24B.1 U4B.30 | length 4.3
  Top Layer w0.2: U4B.30@79,78.598 79,77.75 79.75,77 79.75,75.7 80.475,74.975 C24B.1@80.5,74.975
NetC24B_2: C24B.2 U4B.31 | length 2.5
  Top Layer w0.2: U4B.31@79.5,78.598 79.5,77.75 80.133,77.117 80.133,76.874 80.482,76.525 C24B.2@80.5,76.525
NetC24C_1: C24C.1 U4C.30 | length 4.3
  Top Layer w0.2: U4C.30@83.25,60.598 83.25,59.738 84,58.988 84,57.7 84.725,56.975 C24C.1@84.75,56.975
NetC24C_2: C24C.2 U4C.31 | length 2.8
  Top Layer w0.2: U4C.31@83.75,60.598 83.75,59.75 84,59.5 84.5,59.5 84.75,59.25 C24C.2@84.75,58.525
NetC24D_1: C24D.1 U4D.30 | length 4.3
  Top Layer w0.2: C24D.1@165.25,125.025 165.275,125.025 166,124.3 166,123.012 166.75,122.262 U4D.30@166.75,121.402
NetC24D_2: C24D.2 U4D.31 | length 2.8
  Top Layer w0.2: C24D.2@165.25,123.475 165.25,122.75 165.5,122.5 166,122.5 166.25,122.25 U4D.31@166.25,121.402
NetC24E_1: C24E.1 U4E.30 | length 4.3
  Top Layer w0.2: C24E.1@165.25,99.025 165.275,99.025 166,98.3 166,97.012 166.75,96.262 U4E.30@166.75,95.402
NetC24E_2: C24E.2 U4E.31 | length 2.8
  Top Layer w0.2: C24E.2@165.25,97.475 165.25,96.75 165.5,96.5 166,96.5 166.25,96.25 U4E.31@166.25,95.402
NetC24F_1: C24F.1 U4F.30 | length 4.3
  Top Layer w0.2: C24F.1@165.25,73.025 165.275,73.025 166,72.3 166,71.012 166.75,70.262 U4F.30@166.75,69.402
NetC24F_2: C24F.2 U4F.31 | length 2.8
  Top Layer w0.2: C24F.2@165.25,71.475 165.25,70.75 165.5,70.5 166,70.5 166.25,70.25 U4F.31@166.25,69.402
NetC25A_2: C25A.2 C33A.2 U4A.12 | length 3.7
  Top Layer w0.2: U4A.12@79.75,130.652 79.75,131.95 80.525,132.725 C25A.2@80.525,132.75 C33A.2@80.525,134
NetC25B_2: C25B.2 C33B.2 U4B.12 | length 3.7
  Top Layer w0.2: U4B.12@78.5,83.902 78.527,83.929 78.527,84.714 79.037,85.224 79.037,85.762 C25B.2@79.275,86 C33B.2@79.275,87.25
NetC25C_2: C25C.2 C33C.2 U4C.12 | length 3.7
  Top Layer w0.2: U4C.12@82.75,65.902 82.75,67.2 83.525,67.975 C25C.2@83.525,68 C33C.2@83.525,69.25
NetC25D_2: C25D.2 C33D.2 U4D.12 | length 3.7
  Top Layer w0.2: C33D.2@166.475,112.75 C25D.2@166.475,114 166.475,114.025 167.25,114.8 U4D.12@167.25,116.098
NetC25E_2: C25E.2 C33E.2 U4E.12 | length 3.7
  Top Layer w0.2: C33E.2@166.475,86.75 C25E.2@166.475,88 166.475,88.025 167.25,88.8 U4E.12@167.25,90.098
NetC25F_2: C25F.2 C33F.2 U4F.12 | length 3.7
  Top Layer w0.2: C33F.2@166.475,60.75 C25F.2@166.475,62 166.475,62.025 167.25,62.8 U4F.12@167.25,64.098
NetC26A_1: C26A.1 C28A.2 | length 3.3
  Top Layer w0.2: C28A.2@78.75,121.725 78.732,121.725 78.383,121.376 78.383,121.358 78.25,121.225 78.25,119.8 79.025,119.025 C26A.1@79.025,119
NetC26A_2: C26A.2 C29A.1 C125A.1 D8A.C U4A.25 | length 25.8
  Top Layer w0.2: C26A.2@77.475,119 77.475,119.018 77.126,119.367 77.108,119.367 76.75,119.725 76.75,122.55 77.475,123.275 C29A.1@77.5,123.275
  Top Layer w0.3: C29A.1@77.5,123.275 v1(77.5,124.25) 77.5,124.345 77.75,124.595 U4A.25@77.75,125.323 ; v1(81.25,136.75) D8A.C@81.25,138.213 81.287,138.25 C125A.1@84.5,138.25
  Bottom Layer w0.3: v1(77.5,124.25) 77.5,133 v1(81.25,136.75)
NetC26B_1: C26B.1 C28B.2 | length 4.7
  Top Layer w0.2: C26B.1@73.475,76.5 73.475,76.475 74.2,75.75 76.7,75.75 77.475,74.975 C28B.2@77.5,74.975
NetC26B_2: C26B.2 C29B.1 C125B.1 D8B.C U4B.25 | length 23.5
  Top Layer w0.2: C26B.2@75.025,76.5 75.05,76.525 C29B.1@76.25,76.525 76.25,77.175 76.5,77.425 v1(76.5,77.5)
  Top Layer w0.3: v1(76.5,77.5) U4B.25@76.5,78.573 ; v1(80.361,88.611) 81.165,88.611 81.286,88.732 83.232,88.732 D8B.C@83.25,88.713 83.287,88.75 C125B.1@86.75,88.75
  Bottom Layer w0.3: v1(76.5,77.5) 76,78 76,85 79.725,88.725 79.772,88.678 80.294,88.678 v1(80.361,88.611)
NetC26C_1: C26C.1 C28C.2 | length 4.7
  Top Layer w0.2: C26C.1@77.725,58.5 77.725,58.475 78.45,57.75 80.95,57.75 81.725,56.975 C28C.2@81.75,56.975
NetC26C_2: C26C.2 C29C.1 C125C.1 D8C.C U4C.25 | length 22.3
  Top Layer w0.2: C26C.2@79.275,58.5 79.3,58.525 C29C.1@80.5,58.525
  Top Layer w0.3: C29C.1@80.5,58.525 v1(80.5,59.5) 80.5,59.595 80.75,59.845 U4C.25@80.75,60.573 ; v1(80.5,70.5) 82.787,70.5 84.166,71.879 84.166,71.905 84.511,72.25 D8C.C@84.537,72.25 C125C.1@87.5,72.25
  Bottom Layer w0.3: v1(80.5,59.5) 80.5,59.595 80.25,59.845 80.25,70.155 80.5,70.405 v1(80.5,70.5)
NetC26D_1: C26D.1 C28D.2 | length 4.7
  Top Layer w0.2: C28D.2@168.25,125.025 168.275,125.025 169.05,124.25 171.55,124.25 172.275,123.525 C26D.1@172.275,123.5
NetC26D_2: C26D.2 C29D.1 C125D.1 D8D.C U4D.25 | length 21.2
  Top Layer w0.2: C29D.1@169.5,123.475 170.7,123.475 C26D.2@170.725,123.5
  Top Layer w0.3: C125D.1@163.75,110 D8D.C@167.25,110 167.471,110.221 168.221,110.221 v1(169.5,111.5) ; U4D.25@169.25,121.427 169.25,122.155 169.5,122.405 v1(169.5,122.5) C29D.1@169.5,123.475
  Bottom Layer w0.3: v1(169.5,111.5) 170,112 170,122 v1(169.5,122.5)
NetC26E_1: C26E.1 C28E.2 | length 4.7
  Top Layer w0.2: C28E.2@168.25,99.025 168.275,99.025 169.05,98.25 171.55,98.25 172.275,97.525 C26E.1@172.275,97.5
NetC26E_2: C26E.2 C29E.1 C125E.1 D8E.C U4E.25 | length 21.4
  Top Layer w0.2: C29E.1@169.5,97.475 170.7,97.475 C26E.2@170.725,97.5
  Top Layer w0.3: C125E.1@163.75,84 D8E.C@167.213,84 168.25,84 v1(169.5,85.25) ; U4E.25@169.25,95.427 169.25,96.155 169.5,96.405 v1(169.5,96.5) C29E.1@169.5,97.475
  Bottom Layer w0.3: v1(169.5,85.25) 170,85.75 170,96.095 169.595,96.5 v1(169.5,96.5)
NetC26F_1: C26F.1 C28F.2 | length 4.7
  Top Layer w0.2: C28F.2@168.25,73.025 168.275,73.025 169.05,72.25 171.55,72.25 172.275,71.525 C26F.1@172.275,71.5
NetC26F_2: C26F.2 C29F.1 C125F.1 D8F.C U4F.25 | length 21.2
  Top Layer w0.2: C29F.1@169.5,71.475 170.7,71.475 C26F.2@170.725,71.5
  Top Layer w0.3: C125F.1@163.75,58 D8F.C@167.213,58 167.222,58.008 168.008,58.008 v1(169.5,59.5) ; U4F.25@169.25,69.427 169.25,70.155 169.5,70.405 v1(169.5,70.5) C29F.1@169.5,71.475
  Bottom Layer w0.3: v1(169.5,59.5) 170,60 170,70 v1(169.5,70.5)
NetC27A_1: C27A.1 U4A.29 | length 2.3
  Top Layer w0.2: U4A.29@79.75,125.348 79.75,124.493 80.25,123.993 C27A.1@80.25,123.275
NetC27A_2: C27A.2 U4A.28 | length 4.1
  Top Layer w0.2: U4A.28@79.25,125.348 79.25,124.25 79.5,124 79.5,122.45 80.225,121.725 C27A.2@80.25,121.725
NetC27B_1: C27B.1 U4B.29 | length 2.3
  Top Layer w0.2: U4B.29@78.5,78.598 78.5,77.75 79,77.25 C27B.1@79,76.525
NetC27B_2: C27B.2 U4B.28 | length 4.1
  Top Layer w0.2: U4B.28@78,78.598 78,77.5 78.25,77.25 78.25,75.7 78.975,74.975 C27B.2@79,74.975
NetC27C_1: C27C.1 U4C.29 | length 2.3
  Top Layer w0.2: U4C.29@82.75,60.598 82.75,59.743 83.25,59.243 C27C.1@83.25,58.525
NetC27C_2: C27C.2 U4C.28 | length 4.1
  Top Layer w0.2: U4C.28@82.25,60.598 82.25,59.5 82.5,59.25 82.5,57.7 83.225,56.975 C27C.2@83.25,56.975
NetC27D_1: C27D.1 U4D.29 | length 2.3
  Top Layer w0.2: C27D.1@166.75,123.475 166.75,122.757 167.25,122.257 U4D.29@167.25,121.402
NetC27D_2: C27D.2 U4D.28 | length 4.1
  Top Layer w0.2: C27D.2@166.75,125.025 166.775,125.025 167.5,124.3 167.5,122.75 167.75,122.5 U4D.28@167.75,121.402
NetC27E_1: C27E.1 U4E.29 | length 2.3
  Top Layer w0.2: C27E.1@166.75,97.475 166.75,96.757 167.25,96.257 U4E.29@167.25,95.402
NetC27E_2: C27E.2 U4E.28 | length 4.1
  Top Layer w0.2: C27E.2@166.75,99.025 166.775,99.025 167.5,98.3 167.5,96.75 167.75,96.5 U4E.28@167.75,95.402
NetC27F_1: C27F.1 U4F.29 | length 2.3
  Top Layer w0.2: C27F.1@166.75,71.475 166.75,70.757 167.25,70.257 U4F.29@167.25,69.402
NetC27F_2: C27F.2 U4F.28 | length 4.1
  Top Layer w0.2: C27F.2@166.75,73.025 166.775,73.025 167.5,72.3 167.5,70.75 167.75,70.5 U4F.28@167.75,69.402
NetC28A_1: C28A.1 U4A.27 | length 2.1
  Top Layer w0.2: C28A.1@78.75,123.275 U4A.27@78.75,125.348
NetC28B_1: C28B.1 U4B.27 | length 2.1
  Top Layer w0.2: C28B.1@77.5,76.525 U4B.27@77.5,78.598
NetC28C_1: C28C.1 U4C.27 | length 2.1
  Top Layer w0.2: C28C.1@81.75,58.525 U4C.27@81.75,60.598
NetC28D_1: C28D.1 U4D.27 | length 2.1
  Top Layer w0.2: U4D.27@168.25,121.402 C28D.1@168.25,123.475
NetC28E_1: C28E.1 U4E.27 | length 2.1
  Top Layer w0.2: U4E.27@168.25,95.402 C28E.1@168.25,97.475
NetC28F_1: C28F.1 U4F.27 | length 2.1
  Top Layer w0.2: U4F.27@168.25,69.402 C28F.1@168.25,71.475
NetC29A_2: C29A.2 C30A.1 | length 1.5
  Top Layer w0.2: C30A.1@77.475,120.25 77.475,121.7 C29A.2@77.5,121.725
NetC29B_2: C29B.2 C30B.1 | length 1.2
  Top Layer w0.2: C30B.1@75.025,75 75.05,74.975 C29B.2@76.25,74.975
NetC29C_2: C29C.2 C30C.1 | length 1.3
  Top Layer w0.2: C30C.1@79.275,57 79.3,56.975 80.45,56.975 80.475,56.95 C29C.2@80.5,56.975
NetC29D_2: C29D.2 C30D.1 | length 1.3
  Top Layer w0.2: C29D.2@169.5,125.025 169.525,125.05 169.55,125.025 170.7,125.025 C30D.1@170.725,125
NetC29E_2: C29E.2 C30E.1 | length 1.3
  Top Layer w0.2: C29E.2@169.5,99.025 169.525,99.05 169.55,99.025 170.7,99.025 C30E.1@170.725,99
NetC29F_2: C29F.2 C30F.1 | length 1.3
  Top Layer w0.2: C29F.2@169.5,73.025 169.525,73.05 169.55,73.025 170.7,73.025 C30F.1@170.725,73
NetC34A_1: C34A.1 U5A.30 | length 3.9
  Top Layer w0.2: U5A.30@94.5,191.848 94.5,188.95 95.225,188.225 C34A.1@95.25,188.225
NetC34A_2: C34A.2 U5A.31 | length 2.2
  Top Layer w0.2: U5A.31@95,191.848 95,190.85 95.25,190.6 C34A.2@95.25,189.775
NetC34B_1: C34B.1 U5B.30 | length 3.9
  Top Layer w0.2: C34B.1@153.75,199.025 153.775,199.025 154.5,198.3 U5B.30@154.5,195.402
NetC34B_2: C34B.2 U5B.31 | length 2.2
  Top Layer w0.2: C34B.2@153.75,197.475 153.75,196.65 154,196.4 U5B.31@154,195.402
NetC35A_2: C35A.2 C43A.2 U5A.12 | length 3.6
  Top Layer w0.2: U5A.12@94,197.152 94,198.693 94.525,199.218 C43A.2@94.525,199.25 C35A.2@94.525,200.5
NetC35B_2: C35B.2 C43B.2 U5B.12 | length 3.6
  Top Layer w0.2: C35B.2@154.475,186.75 C43B.2@154.475,188 154.475,188.032 155,188.557 U5B.12@155,190.098
NetC36A_1: C36A.1 C38A.2 | length 4.7
  Top Layer w0.2: C36A.1@88.225,189.75 88.225,189.725 88.95,189 91.45,189 92.225,188.225 C38A.2@92.25,188.225
NetC36A_2: C36A.2 C39A.1 C126A.1 D9A.C U5A.25 | length 17.6
  Top Layer w0.3: C36A.2@89.775,189.75 89.8,189.775 C39A.1@91,189.775 v1(91,191) 91.675,191 92,191.325 U5A.25@92,191.823 ; v1(91,186.75) 94.75,183 C126A.1@95.75,183 D9A.C@98.713,183
  Bottom Layer w0.3: v1(91,186.75) v1(91,191)
NetC36B_1: C36B.1 C38B.2 | length 4.7
  Top Layer w0.2: C38B.2@156.75,199.025 156.775,199.025 157.525,198.275 160,198.275 160.408,197.867 160.426,197.867 160.775,197.518 C36B.1@160.775,197.5
NetC36B_2: C36B.2 C39B.1 C126B.1 D9B.C U5B.25 | length 23.6
  Top Layer w0.3: U5B.25@157,195.427 157,195.925 157.325,196.25 v1(158.5,196.25) 158.5,197 158.275,197.225 C39B.1@158.275,197.475 ; C39B.1@158,197.475 C39B.1@158.275,197.475 ; C36B.2@159.225,197.5 159.2,197.475 C39B.1@158.275,197.475 ; v1(160.25,182.5) 160.268,182.482 160.268,180.768 D9B.C@160.287,180.75 C126B.1@163,180.75
  Bottom Layer w0.3: v1(158.5,196.25) 159.375,195.375 159.375,183.375 v1(160.25,182.5)
NetC37A_1: C37A.1 U5A.29 | length 2.2
  Top Layer w0.2: C37A.1@93.75,189.775 93.75,190.493 94,190.743 U5A.29@94,191.848
NetC37A_2: C37A.2 U5A.28 | length 4.1
  Top Layer w0.2: U5A.28@93.5,191.848 93.5,190.738 93.025,190.263 93.025,188.925 93.725,188.225 C37A.2@93.75,188.225
NetC37B_1: C37B.1 U5B.29 | length 2.2
  Top Layer w0.2: U5B.29@155,195.402 155,196.507 155.25,196.757 C37B.1@155.25,197.475
NetC37B_2: C37B.2 U5B.28 | length 4.1
  Top Layer w0.2: C37B.2@155.25,199.025 155.275,199.025 155.975,198.325 155.975,196.725 155.5,196.25 U5B.28@155.5,195.402
NetC38A_1: C38A.1 U5A.27 | length 2.4
  Top Layer w0.2: C38A.1@92.25,189.775 92.25,190.5 92.973,191.223 92.973,191.821 U5A.27@93,191.848
NetC38B_1: C38B.1 U5B.27 | length 2.4
  Top Layer w0.2: U5B.27@156,195.402 156.027,195.429 156.027,196.027 156.75,196.75 C38B.1@156.75,197.45
NetC39A_2: C39A.2 C40A.1 | length 1.2
  Top Layer w0.2: C40A.1@89.775,188.25 89.8,188.225 C39A.2@91,188.225
NetC39B_2: C39B.2 C40B.1 | length 1.2
  Top Layer w0.2: C39B.2@158,199.025 159.2,199.025 C40B.1@159.225,199
NetC44A_1: C44A.1 U6A.30 | length 3.9
  Top Layer w0.2: U6A.30@93.5,155.848 93.5,152.95 94.225,152.225 C44A.1@94.25,152.225
NetC44A_2: C44A.2 U6A.31 | length 2.2
  Top Layer w0.2: U6A.31@94,155.848 94,154.85 94.25,154.6 C44A.2@94.25,153.775
NetC44B_1: C44B.1 U6B.30 | length 5.6
  Top Layer w0.2: C44B.1@155.5,146.025 155.525,146.025 156.275,145.275 156.275,143.987 156.982,143.28 157.22,143.28 157.973,142.527 157.973,141.679 U6B.30@158,141.652
NetC44B_2: C44B.2 U6B.31 | length 4.1
  Top Layer w0.2: C44B.2@155.5,144.475 155.5,143.652 156.402,142.75 157.25,142.75 157.5,142.5 U6B.31@157.5,141.652
NetC45A_2: C45A.2 C53A.2 U6A.12 | length 3.6
  Top Layer w0.2: U6A.12@93,161.152 93,162.693 93.525,163.218 C45A.2@93.525,163.25 C53A.2@93.525,164.5
NetC45B_2: C45B.2 C53B.2 U6B.12 | length 3.5
  Top Layer w0.2: C53B.2@158.225,133 158.225,133.225 158.25,133.25 158.225,133.275 C45B.2@158.225,134.25 158.225,135.087 158.5,135.362 U6B.12@158.5,136.348
NetC46A_1: C46A.1 C48A.2 | length 4.7
  Top Layer w0.2: C46A.1@87.225,153.75 87.225,153.725 87.95,153 90.45,153 91.225,152.225 C48A.2@91.25,152.225
NetC46A_2: C46A.2 C49A.1 C127A.1 D10A.C U6A.25 | length 24.2
  Top Layer w0.2: C46A.2@88.775,153.75 88.8,153.775 C49A.1@90,153.775
  Top Layer w0.3: C49A.1@90,153.775 90,154.25 v1(90.5,154.75) 91,155.25 U6A.25@91,155.823 ; v1(90.5,165.75) 93.331,165.75 94.581,167 D10A.C@96.287,167 C127A.1@99.25,167
  Bottom Layer w0.3: v1(90.5,154.75) 90.5,154.845 90.25,155.095 90.25,165.405 90.5,165.655 v1(90.5,165.75)
NetC46B_1: C46B.1 C48B.2 | length 4.7
  Top Layer w0.2: C48B.2@158.5,146.025 158.525,146.025 159.3,145.25 161.775,145.25 162.158,144.867 162.176,144.867 162.525,144.518 C46B.1@162.525,144.5
NetC46B_2: C46B.2 C49B.1 C127B.1 D10B.C U6B.25 | length 22.9
  Top Layer w0.3: C49B.1@159.75,144.475 160.95,144.475 160.95,144.443 160.5,143.993 v1(160.5,143) U6B.25@160.5,141.677 ; v1(162.75,133) 164.713,131.037 D10B.C@165.75,131.037 168.389,131.037 168.759,131.407 168.843,131.407 168.935,131.5 C127B.1@169.5,131.5
  Bottom Layer w0.3: v1(160.5,143) 162.75,140.75 v1(162.75,133)
NetC47A_1: C47A.1 U6A.29 | length 2.2
  Top Layer w0.2: C47A.1@92.75,153.775 92.75,154.493 93,154.743 U6A.29@93,155.848
NetC47A_2: C47A.2 U6A.28 | length 4.1
  Top Layer w0.2: U6A.28@92.5,155.848 92.5,154.75 92.025,154.275 92.025,152.925 92.725,152.225 C47A.2@92.75,152.225
NetC47B_1: C47B.1 U6B.29 | length 3.4
  Top Layer w0.2: C47B.1@157,144.475 157.158,144.317 157.158,143.842 158.5,142.5 U6B.29@158.5,141.652
NetC47B_2: C47B.2 U6B.28 | length 5.2
  Top Layer w0.2: C47B.2@157,146.025 157.025,146.025 157.775,145.275 157.775,143.987 159,142.762 U6B.28@159,141.652
NetC48A_1: C48A.1 U6A.27 | length 2.4
  Top Layer w0.2: C48A.1@91.25,153.775 91.408,153.933 91.408,154.408 92,155 U6A.27@92,155.848
NetC48B_1: C48B.1 U6B.27 | length 3.2
  Top Layer w0.2: C48B.1@158.5,144.475 158.5,143.757 159.5,142.757 U6B.27@159.5,141.652
NetC49A_2: C49A.2 C50A.1 | length 1.2
  Top Layer w0.2: C50A.1@88.775,152.25 88.8,152.225 C49A.2@90,152.225
NetC49B_2: C49B.2 C50B.1 | length 1.2
  Top Layer w0.2: C49B.2@159.75,146.025 160.95,146.025 C50B.1@160.975,146
NetC54A_1: C54A.1 C56A.2 | length 1.3
  Top Layer w0.2: C56A.2@73,98.525 73.275,98.25 C54A.1@74.225,98.25
NetC54A_2: C54A.2 C55A.1 D14A.C U7A.13 U7A.29 | length 36.5
  Top Layer w0.2: C54A.2@75.775,98.25 76.038,97.987 76.538,97.987 77.025,97.5 77.5,97.5 v1@77.701,97.701
  Top Layer w0.3: U7A.29@80.5,106.402 80.5,109.155 80.75,109.405 v1(80.75,109.5) ; U7A.13@81,101.098 81,99 v1(81.25,98.75)
  Top Layer w1: v1(78,99) v1(78,98) 78,97 79.808,95.192 81.062,95.192 81.081,95.173 D14A.C@81.081,95 84,95 85.25,96.25 86.66,96.25
  Bottom Layer w1: v1(80.75,109.5) 78,106.75 v1(78,98) 78.225,97.775 80.275,97.775 v1(81.25,98.75)
NetC54B_1: C54B.1 C56B.2 | length 1.3
  Top Layer w0.2: C54B.1@168.275,169.25 168.4,169.375 169.4,169.375 C56B.2@169.5,169.475
NetC54B_2: C54B.2 C55B.1 D14B.C U7B.13 U7B.29 | length 31.7
  Top Layer w0.2: v1(164.25,170.5) 164.25,170.408 164.5,170.158 164.5,169.5 166.475,169.5 C54B.2@166.725,169.25
  Top Layer w0.3: v1(161.25,169.25) 161.5,169 U7B.13@161.5,166.902 ; v1(162,158.75) U7B.29@162,161.598
  Top Layer w1: C55B.1@160.75,173 D14B.C@163.919,173 ; D14B.C@164,173 164,172.617 164.25,172.367 v1(164.25,170.5) v1(164.25,169.5)
  Bottom Layer w1: v1(161.25,169.25) 162.5,170.5 v1(164.25,170.5) 164.25,161 v1(162,158.75)
NetC57A_2: C57A.2 R101A.2 R197A.2 | length 2.7
  Top Layer w0.2: R197A.2@71.475,105.75 71.475,107 R101A.2@71.475,108.5
NetC57B_2: C57B.2 R101B.2 R197B.2 | length 2.7
  Top Layer w0.2: R101B.2@171.025,159.5 C57B.2@171.025,161 R197B.2@171.025,162.25
NetC59A_2: C59A.2 R198A.2 | length 1.3
  Top Layer w0.2: C59A.2@88.275,104.25 R198A.2@88.275,105.5
NetC59B_2: C59B.2 R198B.2 | length 1.3
  Top Layer w0.2: C59B.2@166.5,155.975 R198B.2@167.75,155.975
NetC60_1: C60.1 U8.103 X1.1 | length 11.9
  Top Layer w0.2: U8.103@136.975,57.922 139.5,60.447 139.5,64.75 140.3,65.55 140.3,65.77 141.25,66.72 v1(141.25,66.75)
  Bottom Layer w0.2: v1(141.25,66.75) 141.25,65.725 C60.1@141.475,65.5
NetC61_1: C61.1 U8.102 X1.3 | length 10.8
  Top Layer w0.2: U8.102@137.328,57.568 141.25,61.49 141.25,62.65 X1.3@141.95,63.35 ; X1.3@142.2,63.35 142.25,63.3 v1(142.25,62)
  Bottom Layer w0.2: C61.1@141.025,63.25 141.025,63.232 141.374,62.883 141.392,62.883 142.25,62.025 v1(142.25,62)
NetC75_2: C75.2 Q1.1 U8.154 | length 4.6
  Top Layer w0.2: U8.154@115.854,60.75 117,59.604 v1(117,59.5)
  Bottom Layer w0.2: v1(117,59.5) 117.086,59.414 117.336,59.414 C75.2@117.952,58.798 117.952,58.813 119.099,59.96 Q1.1@119.099,59.982
NetC76_2: C76.2 C77.2 C78.2 C79.2 C80.2 C81.2 C82.2 C83.2 C84.2 C85.2 Q1.3 U8.24 U8.68 U8.100 U8.123 | length 88.4
  Top Layer w0.2: v1(116,44) 117,43 117,42.189 U8.24@116.207,41.396 ; v1(128.75,63.75) 128.75,63.812 129.904,64.966 U8.123@129.904,64.993 ; v1(133,43.25) 134.061,43.25 U8.68@134.854,42.457 ; v1(136.75,55.5) 136.75,55.548 138.036,56.834 U8.100@138.036,56.861
  Bottom Layer w0.2: C84.2@114.952,46.952 C76.2@115.952,45.952 C77.2@116.952,44.952 ; C82.2@127.301,63.545 127.795,63.545 128,63.75 v1(128.75,63.75) 128.75,63 C83.2@128.298,62.548 ; C78.2@132.548,44.452 133,44 v1(133,43.25) ; C81.2@134.798,55.548 135.25,56 136.25,56 v1(136.75,55.5) ; C85.2@135.798,54.548 v1(136.75,55.5) ; C80.2@136.798,53.548 137.5,54.25 137.5,54.75 v1(136.75,55.5)
  Bottom Layer w0.3: C79.2@131.548,43.452 130.487,43.452 125.785,38.75 124.285,38.75 118.101,44.934 116.97,44.934 C77.2@116.952,44.952 v1(116,44) 112.391,47.609 112.391,52.105 119.66,59.374 Q1.3@120.626,59.374 120.626,60.34 124.785,64.5 128,64.5 v1(128.75,63.75) 129.384,63.75 136.75,56.384 v1(136.75,55.5) ; C79.2@131.551,43.455 131.976,43.455 132.181,43.25 v1(133,43.25)
NetC88_1: C88.1 C90.2 | length 1.3
  Top Layer w0.2: C88.1@207.775,49 208,49.225 C90.2@209,49.225
NetC89_1: C89.1 C91.2 | length 3.1
  Top Layer w0.2: C89.1@207.775,47.75 207.775,47.775 208.525,48.525 209.475,48.525 210.225,49.275 C91.2@210.25,49.275
NetC93_1: C93.1 C101.2 | length 5.5
  Top Layer w0.5: C101.2@162.3,49 162.3,48.675 162.625,48.35 162.744,48.35 163.672,47.422 163.672,46.203 164.925,44.95 C93.1@165.25,44.95
NetC94_1: C94.1 C102.2 | length 2.1
  Top Layer w0.5: C102.2@162.3,46.838 162.3,45.275 162.625,44.95 C94.1@162.75,44.95
NetC96_1: C96.1 C103.2 | length 2
  Top Layer w0.5: C96.1@170.25,44.95 170.45,45.15 C103.2@170.45,46.838
NetC96_2: C96.2 C97.2 C98.1 L2.1 U10.31 | length 22.1
  Top Layer w0.3: U10.31@161.227,40.25 162.25,40.25 162.75,39.75
  Top Layer w0.5: 162.75,39.75 166.097,39.75 167,39.75 167.75,40.5 C97.2@167.75,42.05 C96.2@170.25,42.05 ; 166.097,34.653 168,32.75 174.95,32.75 C98.1@175.95,31.75
NetC97_1: C97.1 C104.2 | length 5.4
  Top Layer w0.5: C97.1@167.75,44.95 168.075,44.95 169.203,46.078 169.203,47.547 170.006,48.35 170.125,48.35 170.45,48.675 C104.2@170.45,49
NetC105_1: C105.1 C107.2 | length 2.2
  Top Layer w0.5: C105.1@212.75,41.143 212.938,41.143 213.2,40.88 213.2,40.804 213.493,40.511 C107.2@214.607,40.511
NetC108_1: C108.1 C123.2 | length 3.4
  Top Layer w0.3: C108.1@197.25,39.975 197.275,39.975 197.575,39.675 197.575,39.592 198,39.167 198,37.992 198.417,37.575 198.475,37.575 198.775,37.275 C123.2@198.775,37.25
NetC111_1: C111.1 L4.2 | length 1.6
  Top Layer w0.2: C111.1@52.775,42.25 54.35,42.25 L4.2@54.4,42.3
NetC111_2: C111.2 CR2.2 J3.2 R178.1 | length 18.9
  Top Layer w0.2: J3.2@36.95,43 36.95,42.938 37.892,41.996 46.496,41.996 46.75,42.25 C111.2@51.225,42.25 51.25,42.225 v1(51.25,41.3)
  Bottom Layer w0.2: CR2.2@49.384,42.035 49.684,42.035 50.418,41.3 v1(51.25,41.3) 51.25,42.225 R178.1@51.225,42.25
